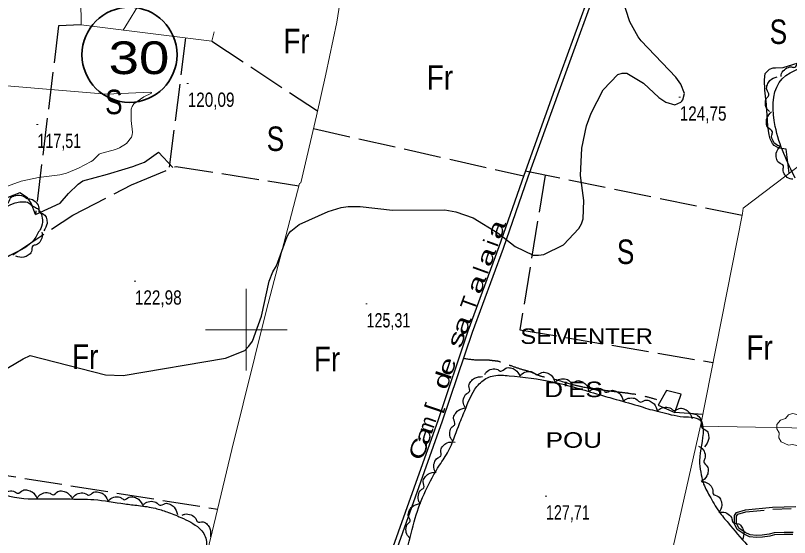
# Model space of a CAD drawing. Extents: x 483847 to 488453, y 4383581 to 4386795.
# Drawn here: x 486358.7 to 486832.5, y 4384372.9 to 4384692.3 of the extents above; entities that cross this region are included whole.
import ezdxf
from ezdxf.enums import TextEntityAlignment as Align

# ---------------------------------------------------------------- set-up
doc = ezdxf.new("R2010")
doc.units = 0
doc.header["$LTSCALE"] = 3.8
doc.linetypes.add('LONG_DASHED', pattern=[7.5, 6, -1.5])
doc.linetypes.add('MEDIUM_DASHED', pattern=[4.5, 3, -1.5])
for name, color, linetype, lineweight in [('1', 7, 'Continuous', 13), ('13', 7, 'Continuous', 25), ('21', 7, 'Continuous', 25), ('25', 7, 'LONG_DASHED', 25), ('27', 7, 'Continuous', 25), ('29', 7, 'Continuous', 13), ('38', 7, 'Continuous', 25), ('51', 7, 'Continuous', 13), ('6', 7, 'Continuous', 35), ('7', 7, 'Continuous', 13), ('8', 7, 'Continuous', 25), ('9', 7, 'Continuous', 13)]:
    doc.layers.add(name, color=color, linetype=linetype, lineweight=lineweight)
doc.layers.add('31', color=7, linetype='Continuous')
doc.layers.add('5', color=7, linetype='Continuous')

msp = doc.modelspace()

# ---------------------------------------------------------------- linework, layer by layer
at = {"layer": '1'}
for p, q in [((486500, 4384525), (486500, 4384475)), ((486475, 4384500), (486525, 4384500))]:
    msp.add_line(p, q, dxfattribs=at)
at = {"layer": '21'}
msp.add_lwpolyline([(486762.22, 4384449.34), (486766.14, 4384460.54), (486757.09, 4384462.77), (486752.16, 4384453.76)], close=True, dxfattribs=at)
at = {"layer": '25'}
for p, q in [((486462.77, 4384678.6), (486452.63, 4384598.17)), ((486478.99, 4384676.56), (486543.55, 4384633.85)), ((486541.09, 4384623.08), (486669.74, 4384594.18)), ((486803.49, 4384569.81), (486670.74, 4384596.94)), ((486779.39, 4384448.2), (486762.22, 4384449.34)), ((486280.07, 4384422.47), (486482.5, 4384390.21))]:
    msp.add_line(p, q, dxfattribs=at)
for points in [[(486398.99, 4384686.56), (486385.1, 4384685.93), (486370.92, 4384570.5), (486386.02, 4384577.49), (486391.06, 4384583.34), (486397.07, 4384589.11), (486399.95, 4384591.02), (486414.94, 4384595.23), (486425.94, 4384598.38), (486430.47, 4384599.89), (486433.26, 4384600.9), (486437.63, 4384602.41), (486446.2, 4384608.59), (486455.02, 4384599.16)], [(486832.37, 4384595.7), (486830.41, 4384610.44), (486826, 4384611.11), (486823.17, 4384612.72), (486822.06, 4384613.86), (486820.6, 4384616.81), (486820.03, 4384619.29), (486819.13, 4384624.56), (486818.35, 4384637.85), (486817.75, 4384642.89), (486817.35, 4384646.57), (486817.14, 4384652.8), (486817.49, 4384656.77), (486820.23, 4384659.44), (486822.5, 4384660.3), (486824, 4384660.28), (486828.65, 4384660.52), (486854.81, 4384668.7)], [(486309.48, 4384514.52), (486393.72, 4384570.1), (486429.78, 4384588.72), (486456.96, 4384599.96), (486532.17, 4384588.12)], [(486682.88, 4384594.46), (486667.5, 4384500), (486785.67, 4384479.92)], [(486370.92, 4384570.5), (486368.39, 4384577.44), (486366.04, 4384580.63), (486361.28, 4384583.7), (486342.87, 4384576.61), (486331.71, 4384567.69), (486325.09, 4384561.33), (486307.85, 4384562.63), (486285.7, 4384561.82), (486269.63, 4384560.62), (486256.63, 4384553.98), (486236.23, 4384544.82), (486230.81, 4384543.17), (486220.16, 4384538.74), (486212.4, 4384535.93), (486199.88, 4384532.06), (486192.09, 4384528.6)]]:
    msp.add_lwpolyline(points, dxfattribs=at)
at = {"layer": '27'}
for points in [[(486835.96, 4384592.7), (486823.77, 4384624.39), (486826.21, 4384651.21), (486848.96, 4384662.59), (486900.17, 4384675.59), (486910.73, 4384700.79), (486957.06, 4384730.05), (486968.43, 4384726.8), (486945.68, 4384704.85), (486928.61, 4384673.97), (486901.79, 4384649.59), (486838.4, 4384591.89)], [(486827.33, 4384654.99), (486827.67, 4384656.73), (486830.1, 4384659.64), (486833.62, 4384660.76), (486835.66, 4384660.56), (486837.8, 4384663.4), (486840.51, 4384664.66), (486843.53, 4384664.69), (486847.8, 4384662.17)], [(486820.24, 4384633.58), (486818.94, 4384634.78), (486817.75, 4384638.38), (486818.65, 4384641.96), (486819.9, 4384643.59), (486818.61, 4384646.91), (486818.95, 4384649.87), (486820.52, 4384652.46), (486824.91, 4384654.77)], [(486826.79, 4384612.28), (486825.09, 4384612.78), (486822.42, 4384615.47), (486821.63, 4384619.08), (486822.03, 4384621.09), (486819.4, 4384623.49), (486818.39, 4384626.3), (486818.65, 4384629.31), (486821.55, 4384633.33)], [(486834.54, 4384592.01), (486832.79, 4384592.3), (486829.81, 4384594.65), (486828.6, 4384598.14), (486828.75, 4384600.19), (486825.85, 4384602.25), (486824.51, 4384604.91), (486824.4, 4384607.94), (486826.8, 4384612.28)], [(485586.07, 4384404.96), (485597.78, 4384411.17), (485606.35, 4384417.2), (485622.8, 4384434.3), (485638.04, 4384445.26), (485644.5, 4384445.62), (485658.99, 4384445.86), (485668.07, 4384446.18), (485677.83, 4384446.56), (485685.78, 4384446.52), (485686.16, 4384446.52), (485695.75, 4384445.63), (485705.07, 4384446.85), (485720.26, 4384453.83), (485731.69, 4384460.95), (485744.83, 4384466.76), (485753.85, 4384468.21), (485762.1, 4384467.94), (485771.46, 4384466.38), (485779.77, 4384465.21), (485792.44, 4384459.25), (485803.25, 4384459.25), (485830.42, 4384465.39), (485855.97, 4384473.28), (485881.92, 4384482.28), (485908.3, 4384490.54), (485915.32, 4384493.44), (485922.33, 4384495.59), (485931.48, 4384495.68), (485950.13, 4384498.57), (485982.66, 4384501.4), (486018.63, 4384502.69), (486042.78, 4384507.44), (486070.69, 4384512.67), (486104.24, 4384513.09), (486123.28, 4384517.17), (486134.56, 4384518.36), (486141.25, 4384519.31), (486150.43, 4384521.51), (486171.2, 4384525.11), (486181.12, 4384526.7), (486198.83, 4384526.52), (486209.89, 4384528.39), (486216.24, 4384532.2), (486231.76, 4384541.73), (486248.98, 4384549.44), (486261.04, 4384553.17), (486271.06, 4384556.25), (486282.21, 4384558.87), (486287.69, 4384558.94), (486300.96, 4384558.6), (486310.55, 4384557.18), (486316.3, 4384555.23), (486321.69, 4384554.32), (486328.92, 4384556.7), (486335.23, 4384562.38), (486343.66, 4384568.94), (486364.13, 4384578.33), (486366, 4384578), (486368.6, 4384576.09), (486369.79, 4384575.39), (486372.24, 4384574.08), (486374.23, 4384571.43), (486375.15, 4384567.21), (486374.25, 4384561.97), (486372.4, 4384559.07), (486370.63, 4384555.87), (486352.9, 4384543.97), (486339.38, 4384532.31), (486332.19, 4384527.76), (486317.97, 4384520.39), (486311.22, 4384515.38), (486308.88, 4384513.84), (486298.76, 4384488.69), (486287.54, 4384464.54), (486285.75, 4384455.41), (486283.18, 4384443.07), (486279.57, 4384432.24), (486279.26, 4384426.39), (486278.79, 4384419.5), (486290, 4384406.28), (486334.09, 4384403.62), (486358.16, 4384397.5), (486380.73, 4384396.58), (486398.89, 4384396.32), (486406.69, 4384396.05), (486425.56, 4384393.46), (486433.95, 4384392.44), (486444.35, 4384390.71), (486451.38, 4384388.51), (486459.96, 4384385.16)], [(486346.14, 4384570.91), (486346.28, 4384572.68), (486348.37, 4384575.85), (486351.74, 4384577.36), (486353.79, 4384577.39), (486355.6, 4384580.45), (486358.14, 4384582.02), (486361.14, 4384582.38), (486365.67, 4384580.37)], [(486366.51, 4384580.01), (486368.28, 4384579.88), (486371.45, 4384577.8), (486372.98, 4384574.43), (486373.01, 4384572.38), (486376.08, 4384570.59), (486377.65, 4384568.05), (486378.03, 4384565.05), (486376.03, 4384560.51)], [(486374.74, 4384559.69), (486375.12, 4384557.96), (486374.06, 4384554.32), (486371.28, 4384551.89), (486369.33, 4384551.26), (486368.5, 4384547.8), (486366.53, 4384545.56), (486363.77, 4384544.33), (486358.85, 4384544.92)], [(486645.93, 4384472.56), (486646.9, 4384474.05), (486650.24, 4384475.84), (486653.92, 4384475.56), (486655.74, 4384474.6), (486658.79, 4384476.44), (486661.77, 4384476.6), (486664.58, 4384475.49), (486667.6, 4384471.56)], [(486667.65, 4384471.74), (486668.81, 4384473.08), (486672.37, 4384474.4), (486675.98, 4384473.64), (486677.65, 4384472.45), (486680.92, 4384473.86), (486683.89, 4384473.62), (486686.53, 4384472.14), (486689, 4384467.84)], [(486459.96, 4384385.16), (486471.27, 4384378.47), (486473.92, 4384375.28), (486475.39, 4384367.53), (486474.06, 4384364.1), (486468.58, 4384332.36), (486456.37, 4384281.06), (486450.57, 4384253.61), (486437.24, 4384218.91), (486433.21, 4384189.18), (486433.99, 4384185.86), (486436.3, 4384184.33), (486436.97, 4384184.32), (486441.1, 4384184.71), (486447.44, 4384187.32), (486451.82, 4384188.91), (486456.5, 4384190.87), (486459.83, 4384192.92), (486472.99, 4384200.46), (486476.65, 4384203.94), (486479.61, 4384206.22), (486488.62, 4384212.32), (486496.68, 4384219.48), (486502, 4384224.06), (486511.41, 4384231.95), (486539.46, 4384262.46), (486556.14, 4384273.86), (486561.61, 4384278.73), (486564.81, 4384282.06), (486575.24, 4384313.88), (486592.54, 4384347.7), (486603.35, 4384384.68), (486618.29, 4384417.11), (486623.74, 4384425.81), (486629.81, 4384440.88), (486633.7, 4384450.43), (486641.19, 4384465.26), (486647.57, 4384470.57), (486651.57, 4384471.86), (486660.8, 4384471.88), (486687.53, 4384468.12), (486716.08, 4384460.28), (486726.32, 4384457.36), (486741.64, 4384452.94), (486747.02, 4384451.28), (486753.15, 4384449.77), (486767.51, 4384446.79), (486778.5, 4384443.85), (486779.56, 4384439.11), (486777.41, 4384419.93), (486778.13, 4384412.87), (486779.55, 4384406.62), (486783.55, 4384398.31), (486789.34, 4384388.7), (486794.95, 4384381.79), (486806.53, 4384368.27), (486812.52, 4384362.18), (486821.5, 4384354.85), (486839.86, 4384348.2), (486856.39, 4384344.37), (486864.63, 4384343.12), (486886.87, 4384340.33), (486895.94, 4384339.52), (486904.04, 4384339.11), (486909.51, 4384338.95), (486913.63, 4384337.99), (486915.08, 4384334.37), (486915.66, 4384328.28), (486915.43, 4384322.74), (486912.42, 4384321.8), (486907.78, 4384322.62), (486895.36, 4384325.35), (486888.93, 4384326.49), (486882.24, 4384325.99), (486876.01, 4384320.37), (486872.23, 4384313.15), (486873.79, 4384307.2), (486881.33, 4384304.54), (486889.2, 4384303.6), (486900.97, 4384303.06), (486911.02, 4384302.54), (486921.15, 4384302.39), (486925.48, 4384301.06), (486928.7, 4384295.53), (486929.06, 4384289.07), (486922.67, 4384283.16), (486903.92, 4384283.43), (486890.73, 4384279.42), (486884.7, 4384267.35), (486876.54, 4384242.48), (486874.52, 4384232.45)], [(486634, 4384452.41), (486633.1, 4384453.94), (486633, 4384457.74), (486634.9, 4384460.9), (486636.57, 4384462.1), (486636.29, 4384465.65), (486637.48, 4384468.38), (486639.74, 4384470.4), (486644.61, 4384471.34)], [(486688.97, 4384467.73), (486690.24, 4384468.97), (486693.89, 4384470), (486697.43, 4384468.93), (486699, 4384467.61), (486702.37, 4384468.74), (486705.31, 4384468.25), (486707.82, 4384466.56), (486709.92, 4384462.07)], [(486709.91, 4384462.04), (486711.2, 4384463.26), (486714.87, 4384464.23), (486718.38, 4384463.12), (486719.93, 4384461.77), (486723.32, 4384462.85), (486726.26, 4384462.33), (486728.74, 4384460.6), (486730.78, 4384456.08)], [(486730.78, 4384456.08), (486732.07, 4384457.3), (486735.74, 4384458.26), (486739.26, 4384457.13), (486740.8, 4384455.77), (486744.19, 4384456.84), (486747.13, 4384456.31), (486749.6, 4384454.57), (486751.62, 4384450.04)], [(486626.24, 4384432.1), (486625.16, 4384433.51), (486624.59, 4384437.26), (486626.08, 4384440.63), (486627.59, 4384442.03), (486626.88, 4384445.51), (486627.72, 4384448.38), (486629.71, 4384450.66), (486634.42, 4384452.19)], [(486751.62, 4384450.02), (486752.81, 4384451.34), (486756.39, 4384452.59), (486759.98, 4384451.75), (486761.63, 4384450.53), (486764.93, 4384451.87), (486767.9, 4384451.57), (486770.5, 4384450.04), (486772.88, 4384445.69)], [(486772.87, 4384448.71), (486774.62, 4384448.41), (486777.58, 4384446.04), (486778.78, 4384442.55), (486778.62, 4384440.5), (486781.51, 4384438.42), (486782.84, 4384435.75), (486782.93, 4384432.73), (486780.51, 4384428.41)], [(486615.66, 4384413.27), (486614.89, 4384414.87), (486615.1, 4384418.65), (486617.25, 4384421.65), (486619.01, 4384422.71), (486619.03, 4384426.27), (486620.44, 4384428.9), (486622.85, 4384430.73), (486627.78, 4384431.26)], [(486776.77, 4384428.68), (486778.37, 4384427.89), (486780.54, 4384424.78), (486780.69, 4384421.1), (486779.96, 4384419.18), (486782.14, 4384416.37), (486782.65, 4384413.43), (486781.88, 4384410.5), (486778.34, 4384407.04)], [(486606.57, 4384393.5), (486605.6, 4384394.99), (486605.31, 4384398.77), (486607.05, 4384402.03), (486608.66, 4384403.31), (486608.21, 4384406.83), (486609.26, 4384409.63), (486611.41, 4384411.75), (486616.23, 4384412.93)], [(486778.79, 4384406.9), (486780.56, 4384406.85), (486783.84, 4384404.94), (486785.53, 4384401.66), (486785.67, 4384399.61), (486788.83, 4384397.98), (486790.53, 4384395.53), (486791.06, 4384392.55), (486789.3, 4384387.91)], [(486350.28, 4384397.92), (486351.26, 4384399.4), (486354.62, 4384401.16), (486358.3, 4384400.86), (486360.11, 4384399.89), (486363.17, 4384401.7), (486366.15, 4384401.84), (486368.96, 4384400.71), (486371.95, 4384396.76)], [(486371.95, 4384396.7), (486372.87, 4384398.22), (486376.16, 4384400.11), (486379.85, 4384399.95), (486381.7, 4384399.06), (486384.68, 4384400.99), (486387.66, 4384401.24), (486390.5, 4384400.22), (486393.65, 4384396.39)], [(486393.66, 4384396.74), (486394.64, 4384398.22), (486398, 4384399.99), (486401.68, 4384399.68), (486403.49, 4384398.71), (486406.55, 4384400.52), (486409.53, 4384400.67), (486412.34, 4384399.54), (486415.33, 4384395.58)], [(486415.24, 4384394.71), (486416.32, 4384396.13), (486419.79, 4384397.66), (486423.44, 4384397.1), (486425.18, 4384396.01), (486428.36, 4384397.61), (486431.34, 4384397.55), (486434.06, 4384396.23), (486436.78, 4384392.09)], [(486436.94, 4384392.77), (486438.21, 4384394), (486441.87, 4384395), (486445.4, 4384393.91), (486446.96, 4384392.57), (486450.34, 4384393.68), (486453.28, 4384393.17), (486455.78, 4384391.46), (486457.85, 4384386.96)], [(486599.9, 4384372.83), (486598.68, 4384374.13), (486597.73, 4384377.8), (486598.87, 4384381.31), (486600.22, 4384382.85), (486599.16, 4384386.25), (486599.7, 4384389.18), (486601.45, 4384391.65), (486605.98, 4384393.66)], [(486789.62, 4384388.08), (486791.37, 4384388.39), (486794.96, 4384387.15), (486797.26, 4384384.27), (486797.79, 4384382.28), (486801.21, 4384381.3), (486803.36, 4384379.23), (486804.46, 4384376.41), (486803.64, 4384371.52)], [(486460.74, 4384386.46), (486462.38, 4384387.13), (486466.15, 4384386.71), (486469.02, 4384384.39), (486469.98, 4384382.57), (486473.53, 4384382.35), (486476.08, 4384380.8), (486477.76, 4384378.29), (486478.02, 4384373.34)]]:
    msp.add_spline(points, degree=3, dxfattribs=at)
at = {"layer": '29'}
msp.add_lwpolyline([(486831.95, 4384429.28), (486827.41, 4384431.4), (486826, 4384433.94), (486826.1, 4384436.92), (486824.73, 4384439.33), (486824.77, 4384442.08), (486826.93, 4384444.68), (486830.12, 4384445.68), (486831.77, 4384447.87), (486834.34, 4384448.7), (486837.2, 4384448.05), (486839.15, 4384445.78), (486841.96, 4384444.96), (486844.09, 4384442.11), (486844.33, 4384438.98), (486842.45, 4384435.83), (486842.45, 4384433.15), (486840.63, 4384430.54), (486837.01, 4384429.2), (486834.24, 4384429.83)], close=True, dxfattribs=at)
at = {"layer": '38'}
for points in [[(486871.62, 4384959.34), (486801.55, 4384921.35), (486796.15, 4384918.79), (486793.78, 4384916.77), (486789.64, 4384913.03), (486787.19, 4384909.74), (486785.59, 4384906.31), (486783.89, 4384903.32), (486782.07, 4384899.65), (486779.7, 4384894.15), (486771.31, 4384868.35), (486749.34, 4384806.96), (486719.71, 4384723.87), (486691.28, 4384645.79), (486672.37, 4384593.39), (486657.19, 4384549.7), (486638.22, 4384498.21), (486619.96, 4384444), (486590.17, 4384360.22), (486574.09, 4384315.2)], [(486715.84, 4384721.3), (486688.69, 4384646.72), (486669.78, 4384594.3), (486654.6, 4384550.63), (486635.63, 4384499.12), (486617.37, 4384444.9), (486587.58, 4384361.15), (486571.6, 4384316.04)], [(486834.56, 4384374.66), (486829.23, 4384374.66), (486823.36, 4384374.45), (486820.37, 4384373.75), (486815.89, 4384373.06), (486812.22, 4384372.88), (486807.98, 4384373.25), (486804.67, 4384374.86), (486800.53, 4384377.78), (486798.74, 4384381.24), (486798.73, 4384386.3), (486800.06, 4384388.2), (486805.47, 4384389.84), (486822.14, 4384391.41), (486836.28, 4384391.88)]]:
    msp.add_lwpolyline(points, dxfattribs=at)
at = {"layer": '38', "linetype": 'MEDIUM_DASHED'}
msp.add_lwpolyline([(486834.72, 4384375.91), (486829.21, 4384375.91), (486823.19, 4384375.7), (486820.13, 4384374.98), (486815.76, 4384374.31), (486812.24, 4384374.13), (486808.32, 4384374.47), (486805.3, 4384375.94), (486801.5, 4384378.62), (486799.99, 4384381.54), (486799.98, 4384385.91), (486800.84, 4384387.13), (486805.71, 4384388.61), (486822.19, 4384390.16), (486836.17, 4384390.64)], dxfattribs=at)
at = {"layer": '38', "linetype": 'LONG_DASHED'}
msp.add_spline([(486632.94, 4384482.51), (486642.78, 4384481.52), (486648.4, 4384481.51), (486651.17, 4384481.17), (486653.87, 4384480.83), (486657.68, 4384479.58), (486662.01, 4384478.01), (486669.33, 4384475.58), (486675.38, 4384473.7), (486678.59, 4384472.22), (486684.34, 4384470.79), (486698.54, 4384466.84), (486705.72, 4384465.08), (486718.97, 4384463.02), (486728.11, 4384461.91), (486733.58, 4384461.23), (486743.46, 4384459.44), (486751.08, 4384457.38)], degree=3, dxfattribs=at)
at = {"layer": '51'}
msp.add_line((486424.65, 4384683.36), (486437.13, 4384703.79), dxfattribs=at)
for points in [[(486589.29, 4384880.5), (486585.74, 4384858.26), (486569.33, 4384770.93), (486562.25, 4384732.39), (486555.47, 4384688.22), (486548.63, 4384656.42), (486542.87, 4384630.84), (486533.42, 4384589.86), (486532.52, 4384589.5), (486512.19, 4384511.3), (486491.17, 4384426.66), (486479.19, 4384376.33), (486459.91, 4384297.67)], [(486398.62, 4384702.09), (486398.99, 4384686.56), (486478.99, 4384676.56), (486480.42, 4384682.16)], [(486874.94, 4384628.04), (486804.16, 4384574.27), (486803.74, 4384571.13), (486777.94, 4384440.94), (486867.51, 4384439.43)], [(486693.65, 4384130.87), (486694.27, 4384131.56), (486699.32, 4384138.77), (486707.39, 4384146.68), (486710.16, 4384151.44), (486711.93, 4384154.79), (486712.95, 4384163.11), (486716.9, 4384182.11), (486726.81, 4384213.86), (486731.04, 4384236.61), (486747.08, 4384303.99), (486778, 4384441.19)]]:
    msp.add_lwpolyline(points, dxfattribs=at)
at = {"layer": '6'}
msp.add_circle((486428.5, 4384668.2), 29.1, dxfattribs=at)
at = {"layer": '7'}
for p, q in [((486463.64, 4384650.73), (486464.64, 4384650.73)), ((486764.79, 4384642.29), (486765.79, 4384642.29)), ((486371.58, 4384625.56), (486372.58, 4384625.56)), ((486431.29, 4384529.71), (486432.29, 4384529.71)), ((486573.06, 4384515.75), (486574.06, 4384515.75)), ((486682.88, 4384398.24), (486683.88, 4384398.24))]:
    msp.add_line(p, q, dxfattribs=at)
at = {"layer": '8'}
msp.add_lwpolyline([(486345.26, 4384471.58), (486363.31, 4384482.23), (486367.69, 4384484.2), (486413.75, 4384472.46), (486424.58, 4384472.07), (486487.21, 4384482.53), (486499.03, 4384487.35), (486501.58, 4384489.88), (486503.81, 4384492.94), (486509.26, 4384508.32), (486513.92, 4384529.77), (486516.25, 4384535.4), (486518.38, 4384539.06), (486524.9, 4384557.09), (486525.97, 4384558.78), (486527.15, 4384560.3), (486532.27, 4384564.36), (486550.09, 4384572.27), (486558.07, 4384574.73), (486562.33, 4384575.43), (486569.73, 4384575.48), (486589.51, 4384573.22), (486621.54, 4384573.36), (486628.32, 4384572.22), (486638.84, 4384568.45), (486654.08, 4384559), (486664.58, 4384550.93), (486675.66, 4384545.7), (486678.84, 4384545.53), (486682.06, 4384545.92), (486694.1, 4384551.93), (486703.54, 4384561.94), (486705.11, 4384564.84), (486706.25, 4384567.8), (486706.6, 4384578.98), (486704.64, 4384594.37), (486705.32, 4384611.03), (486708.28, 4384624.73), (486711.12, 4384632.46), (486718.42, 4384646.68), (486727.5, 4384656.07), (486730.15, 4384656.9), (486732.86, 4384656.97), (486743.15, 4384650.81), (486752.59, 4384642.01), (486756.76, 4384639.16), (486762.36, 4384637.65), (486765.9, 4384639.23), (486766.59, 4384639.92), (486767.15, 4384640.73), (486768.12, 4384644.56), (486766, 4384650.29), (486762.9, 4384654.47), (486741.75, 4384676.65), (486739.79, 4384679.28), (486734.66, 4384688.32), (486730, 4384703.04)], dxfattribs=at)
at = {"layer": '9'}
msp.add_lwpolyline([(486268.68, 4384556.88), (486362.18, 4384590.82), (486372.87, 4384593.03), (486385.95, 4384594.76), (486389.84, 4384595.86), (486397.3, 4384598.82), (486405.01, 4384602.83), (486406.11, 4384603.56), (486410.03, 4384607.4), (486410.73, 4384607.77), (486411.55, 4384608.12), (486419.85, 4384610.3), (486422.29, 4384611.34), (486426.64, 4384613.91), (486429.7, 4384617.89), (486430.11, 4384619.33), (486430.33, 4384620.92), (486429.53, 4384627.91), (486429.49, 4384634.97), (486430.18, 4384636.6), (486431.18, 4384638.11), (486437.35, 4384642.39), (486441.91, 4384644.83), (486441.9, 4384645.18), (486441.34, 4384645.38), (486414.47, 4384644.09), (486323.77, 4384651.6)], dxfattribs=at)

# ---------------------------------------------------------------- texts
at = {"layer": '13', "width": 1.25}
msp.add_text('30', height=20, dxfattribs=at).set_placement((486434.3, 4384656.4), align=Align.CENTER)
at = {"layer": '31'}
for s, width, p in [('S', 0.8, (486825.68, 4384674.81)), ('Fr', 0.85, (486530.69, 4384669.11)), ('Fr', 0.85, (486618.55, 4384646.84)), ('S', 0.8, (486418.92, 4384631.86)), ('S', 0.8, (486517.82, 4384609.34)), ('S', 0.8, (486732.17, 4384540.19)), ('Fr', 0.85, (486814.17, 4384481.59)), ('Fr', 0.85, (486401.35, 4384475.99)), ('Fr', 0.85, (486549.43, 4384474.56))]:
    msp.add_text(s, height=15, dxfattribs=dict(at, width=width)).set_placement(p, align=Align.CENTER)
at = {"layer": '5'}
for s, rotation, width, p in [('a', 70.08, 1.6, (486657.21, 4384559.84)), ('a', 70.08, 1.6, (486651.15, 4384543.13)), ('a', 70.08, 1.6, (486645.09, 4384526.41)), ('T', 70.08, 0.95, (486640.82, 4384514.62)), ('a', 70.08, 1.6, (486636.01, 4384501.34)), ('s', 71.132, 1.6, (486632.9, 4384492.89)), ('e', 71.132, 1.55, (486627.16, 4384476.1)), ('d', 71.132, 1.5, (486624.29, 4384467.68)), ('[', 71.132, 1.2, (486618.54, 4384450.87)), ('m', 71.132, 0.95, (486614.96, 4384440.39)), ('a', 71.132, 1.6, (486612.78, 4384434)), ('C', 71.132, 1.45, (486609.91, 4384425.63))]:
    msp.add_text(s, height=9.49, rotation=rotation, dxfattribs=dict(at, width=width)).set_placement(p, align=Align.CENTER)
for s, p in [('i', (486654.19, 4384551.52)), ('l', (486648.13, 4384534.8))]:
    msp.add_text(s, height=9.49, rotation=70.08, dxfattribs=at).set_placement(p, align=Align.CENTER)
for s, width, p in [('SEMENTER ', 1.15, (486667.71, 4384491.3)), (" D'ES ", 1.25, (486678.02, 4384458.75)), (' POU', 1.25, (486678.83, 4384427.76))]:
    msp.add_text(s, height=9.5, dxfattribs=dict(at, width=width)).set_placement(p)
at = {"layer": '7'}
for s, width, p in [('120,09', 0.8, (486464.14, 4384636.36)), ('124,75', 0.8, (486765.29, 4384627.92)), ('117,51', 0.75, (486372.08, 4384611.19)), ('122,98', 0.8, (486431.79, 4384515.34)), ('125,31', 0.75, (486573.56, 4384501.38)), ('127,71', 0.75, (486683.38, 4384383.87))]:
    msp.add_text(s, height=8.75, dxfattribs=dict(at, width=width)).set_placement(p)

doc.saveas('drawing.dxf')
